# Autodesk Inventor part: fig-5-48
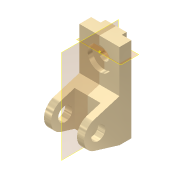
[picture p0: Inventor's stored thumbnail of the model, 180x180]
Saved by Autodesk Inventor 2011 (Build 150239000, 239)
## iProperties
Shininess: 65.0
Angle Display Precision: 2
Document Length Units: 11269
Document Angle Units: 11279
Document Time Units: 11290
Document Mass Units: 11283
Document Length Units Precision: 3
Document Angle Units Precision: 2
Created: 2001-11
Part Number: fig-5-48
Document SubType Name: Modeling
Designer: Renu Muthoo
Density: 1 g/cm^3
Density: 0.0
Volumn: 0.0
Area: 0.0
PropertySet Name: Model Information
Control State: 0
Master: False
Checked Out: False
Author: Renu Muthoo
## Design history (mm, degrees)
node "Sketch1"
sketch "Sketch2"
  geometry: L1 (33.257, 104.664)-(33.257, -75.336); L2 (33.257, -75.336)-(8.257, -75.336); L3 (8.257, -75.336)-(-45.451, -59.045); L4 (-45.451, -1.628)-(8.257, 14.664); L5 (8.257, 14.664)-(8.257, 104.664); L6 (8.257, 104.664)-(33.257, 104.664); C1 r 15 at (-36.743, -30.336); A1 r 30 centre (-36.743, -30.336) between (-45.451, -1.628) and (-45.451, -59.045)
  constraints: 12 end point, 2 centre point, 2 equal length, 2 parallel, 2 point on circle, 2 tangent, 1 coincident, 1 perpendicular, 1 vertical
  dimensions: "d0" = 180 distance of L1.start L1.end; "d1" = 30 radius of A1; "d2" = 25 distance of L5.end L1.start; "d3" = 45 distance from line of L2 A1.centre; "d4" = 70 distance from line of L1 A1.centre; "d5" = 30 diameter of C1
extrude "Extrusion1" new body sketch "Sketch2" distance "d6" = 85; taper "d7" = 0 deg
workplane "Work Plane1"
sketch "Sketch3"
  geometry: L1 (15, 62.364)-(70, 62.364); L2 (70, 62.364)-(70, -52.386); L3 (70, -52.386)-(15, -52.386); L4 (15, -52.386)-(15, 62.364); L5 (0, -45)-(0, -28.708) reference
  constraints: 8 end point, 2 parallel, 1 horizontal, 1 perpendicular
  dimensions: "d8" = 55 distance of L1.start L1.end; "d9" = 15 distance between parallel lines of L5 L4
extrude "Extrusion2" cut sketch "Sketch3" distance "d10" = 50; taper "d11" = 0 deg
sketch "Sketch4"
  geometry: L1 (0, 25)-(85, 25) reference; L2 (0, 0)-(0, 25) reference; L3 (20, 25)-(65, 25); L4 (65, 25)-(65, 35); L5 (65, 35)-(20, 35); L6 (20, 35)-(20, 25)
  constraints: 8 end point, 2 parallel, 1 horizontal, 1 perpendicular, 1 point on line
  dimensions: "d12" = 45 distance of L4.end L5.end; "d13" = 10 distance of L3.end L4.end; "d14" = 20 distance between parallel lines of L2 L6
extrude "Extrusion3" join sketch "Sketch4" stored distance "d15" = 50; taper "d16" = 0 deg
sketch "Sketch5"
  geometry: L1 (85, 0)-(85, 90) reference; L2 (0, 90)-(85, 90) reference; 1 further point
  dimensions: "d17" = 42 distance from line of L2 point (42.5, 48); "d18" = 42.5 distance from line of L1 point (42.5, 48)
hole "Hole1" sketch "Sketch5" at (42.5, 48) diameter "d19" = 20; stored, may be unused: countersink angle "d23" = 82 deg, drill point angle "d25" = 118 deg; dims "d20" = 6, "d21" = 50, "d22" = 10, "d24" = 8
workpoint "Work Point9"
  workplane "Work Plane8"
  workplane "Work Plane12"
body "Solid1"
